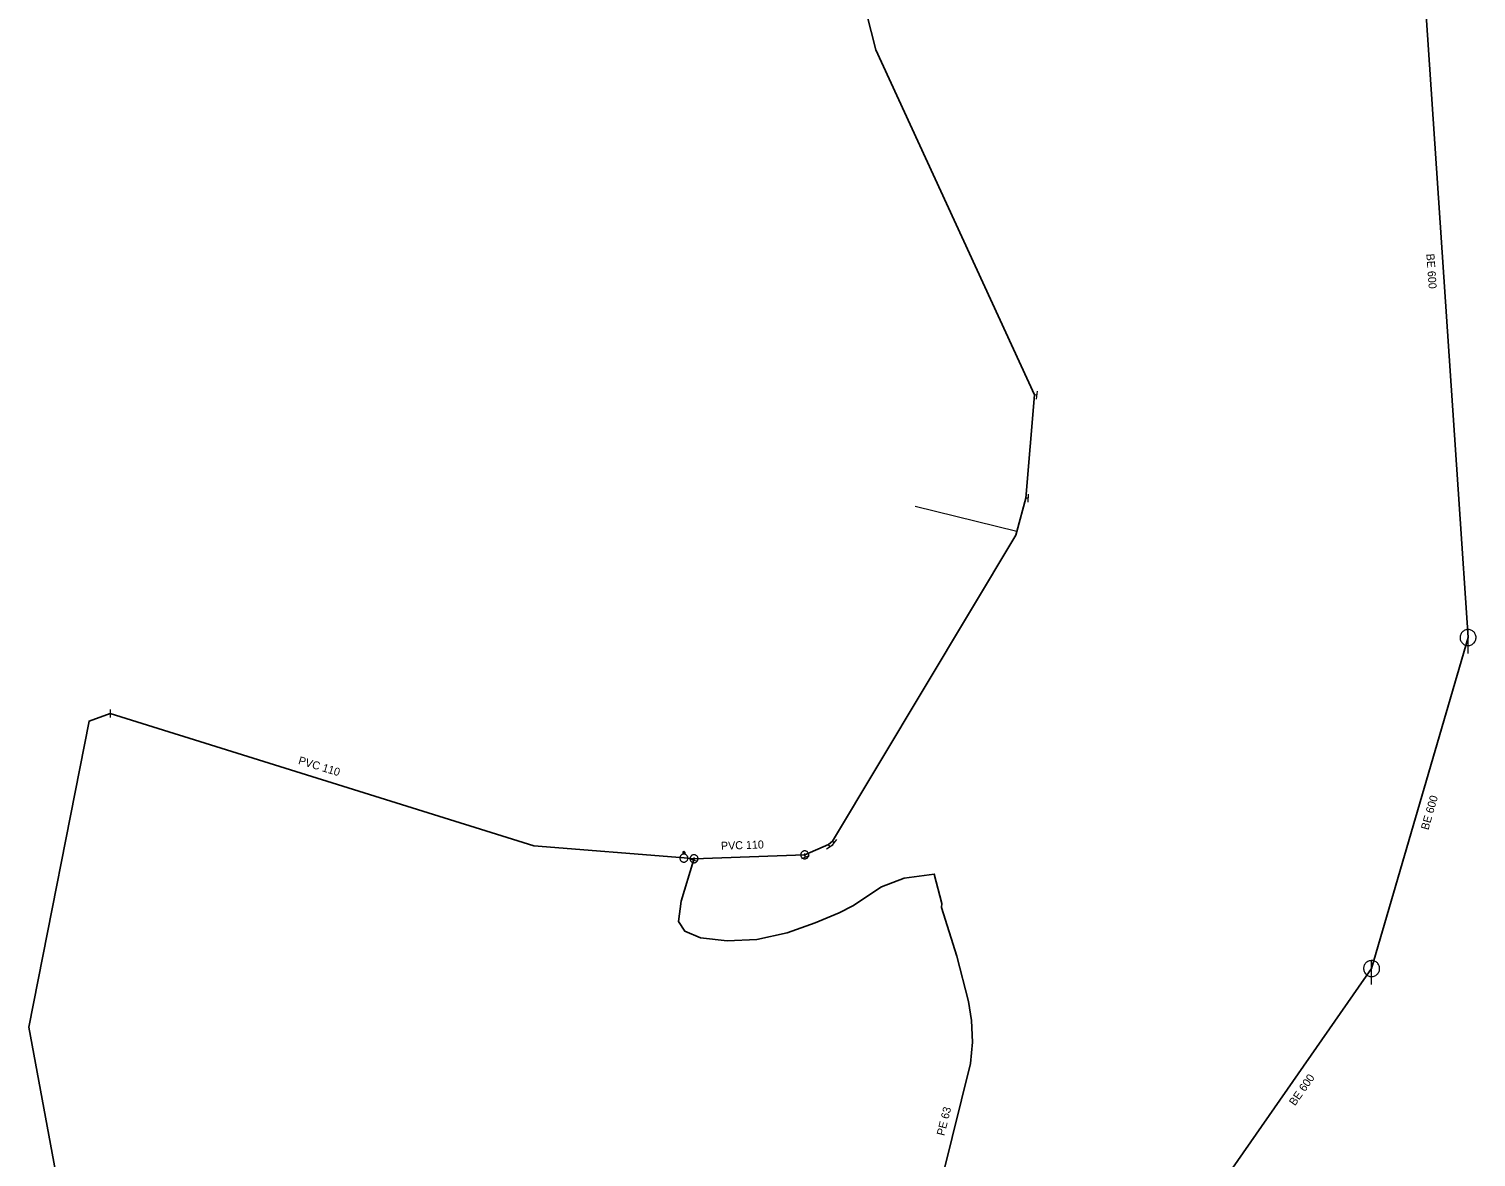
# Model space of a CAD drawing. Extents: x -659250 to -657316, y -997555 to -993684.
# Drawn here: x -658712.7 to -658531.9, y -994490.8 to -994349.9 of the extents above; entities that cross this region are included whole.
import ezdxf

# ---------------------------------------------------------------- set-up
doc = ezdxf.new("R2010")
doc.units = 0
doc.header["$LTSCALE"] = 0.4
doc.layers.add('1', color=7, linetype='Continuous')
for name, color, linetype, lineweight in [('13', 7, 'Continuous', 13), ('14', 7, 'Continuous', 25), ('17', 7, 'Continuous', 25), ('22', 7, 'Continuous', 13), ('23', 7, 'Continuous', 13), ('34', 7, 'Continuous', 13), ('47', 7, 'Continuous', 13)]:
    doc.layers.add(name, color=color, linetype=linetype, lineweight=lineweight)

msp = doc.modelspace()

# ---------------------------------------------------------------- linework, layer by layer
at = {"layer": '13'}
msp.add_line((-658589.278, -994412.67), (-658602.002, -994409.563), dxfattribs=at)
at = {"layer": '14', "lineweight": 13}
for p, q in [((-658586.789, -994395.629), (-658587.086, -994395.585)), ((-658587.859, -994408.51), (-658588.159, -994408.494)), ((-658612.66, -994452.039), (-658612.825, -994451.789)), ((-658612.1, -994451.55), (-658612.337, -994451.366)), ((-658629.622, -994453.55), (-658629.689, -994453.769)), ((-658615.69, -994453.34), (-658615.8, -994453.061))]:
    msp.add_line(p, q, dxfattribs=at)
at = {"layer": '14'}
msp.add_lwpolyline([(-658665.989, -994692.25), (-658669.32, -994646.26), (-658665.8, -994630.84), (-658645.039, -994594.649), (-658628.309, -994572.48), (-658618.039, -994539.21), (-658605.98, -994522.41), (-658563.96, -994494.52), (-658544.98, -994467.27), (-658532.93, -994425.92), (-658538.989, -994335.809)], dxfattribs=at)
at = {"layer": '17'}
for p, q in [((-658629.622, -994453.55), (-658630.87, -994453.45)), ((-658615.8, -994453.061), (-658629.622, -994453.55))]:
    msp.add_line(p, q, dxfattribs=at)
for points in [[(-658613.3, -994213.989), (-658613.524, -994214.403), (-658623.307, -994229.89), (-658624.14, -994257.537), (-658615.692, -994317.956), (-658606.899, -994352.517), (-658587.086, -994395.585), (-658588.159, -994408.494), (-658589.278, -994412.67), (-658589.404, -994413.139), (-658612.337, -994451.366), (-658612.825, -994451.789), (-658615.8, -994453.061)], [(-658702.57, -994435.41), (-658705.199, -994436.353), (-658712.71, -994474.592), (-658701.204, -994536.879), (-658692.771, -994555.022), (-658691.405, -994641.16), (-658677.627, -994701.215), (-658678.449, -994734.261), (-658664.614, -994780.175), (-658662.973, -994794.498), (-658662.386, -994819.574), (-658666.489, -994850.982), (-658664.028, -994890.978), (-658664.848, -994896.368), (-658669.708, -994912.272), (-658675.921, -994922.23), (-658689.166, -994922.67)], [(-658630.87, -994453.45), (-658649.618, -994451.947), (-658702.57, -994435.41)], [(-658629.689, -994453.769), (-658631.25, -994458.87), (-658631.57, -994461.379), (-658630.77, -994462.61), (-658628.829, -994463.44), (-658625.494, -994463.806), (-658621.773, -994463.622), (-658617.987, -994462.818), (-658614.486, -994461.561), (-658611.497, -994460.305), (-658609.78, -994459.44), (-658606.21, -994457.059), (-658603.359, -994455.96), (-658599.62, -994455.469), (-658598.66, -994459.129), (-658598.69, -994459.649), (-658596.8, -994465.719), (-658595.32, -994471.379), (-658594.949, -994473.75), (-658594.84, -994476.46), (-658595.09, -994479.149), (-658598.52, -994492.92)]]:
    msp.add_lwpolyline(points, dxfattribs=at)
at = {"layer": '22'}
for p, q in [((-658532.93, -994427.92), (-658532.929, -994424.92)), ((-658544.98, -994469.27), (-658544.979, -994466.27))]:
    msp.add_line(p, q, dxfattribs=at)
for points in [[(-658531.93, -994425.92), (-658531.935, -994425.811), (-658531.953, -994425.703), (-658531.983, -994425.597), (-658532.023, -994425.496), (-658532.075, -994425.399), (-658532.137, -994425.309), (-658532.209, -994425.226), (-658532.289, -994425.152), (-658532.377, -994425.086), (-658532.471, -994425.031), (-658532.571, -994424.986), (-658532.676, -994424.953), (-658532.783, -994424.931), (-658532.892, -994424.921), (-658533.002, -994424.923), (-658533.11, -994424.937), (-658533.217, -994424.962), (-658533.32, -994424.999), (-658533.418, -994425.048), (-658533.51, -994425.106), (-658533.596, -994425.175), (-658533.673, -994425.252), (-658533.742, -994425.338), (-658533.801, -994425.43), (-658533.849, -994425.528), (-658533.886, -994425.631), (-658533.912, -994425.738), (-658533.926, -994425.846), (-658533.929, -994425.956), (-658533.919, -994426.065), (-658533.898, -994426.172), (-658533.864, -994426.276), (-658533.82, -994426.376), (-658533.765, -994426.471), (-658533.699, -994426.559), (-658533.625, -994426.639), (-658533.542, -994426.711), (-658533.452, -994426.773), (-658533.356, -994426.825), (-658533.254, -994426.866), (-658533.149, -994426.896), (-658533.041, -994426.914), (-658532.931, -994426.92), (-658532.822, -994426.914), (-658532.714, -994426.896), (-658532.609, -994426.867), (-658532.507, -994426.826), (-658532.41, -994426.774), (-658532.32, -994426.712), (-658532.237, -994426.641), (-658532.162, -994426.561), (-658532.097, -994426.473), (-658532.041, -994426.379), (-658531.997, -994426.279), (-658531.963, -994426.175), (-658531.941, -994426.067), (-658531.931, -994425.958)], [(-658543.98, -994467.27), (-658543.985, -994467.161), (-658544.003, -994467.053), (-658544.033, -994466.947), (-658544.073, -994466.846), (-658544.125, -994466.749), (-658544.187, -994466.659), (-658544.259, -994466.576), (-658544.339, -994466.502), (-658544.427, -994466.436), (-658544.521, -994466.381), (-658544.621, -994466.336), (-658544.726, -994466.303), (-658544.833, -994466.281), (-658544.942, -994466.271), (-658545.052, -994466.273), (-658545.16, -994466.287), (-658545.267, -994466.312), (-658545.37, -994466.349), (-658545.468, -994466.398), (-658545.56, -994466.456), (-658545.646, -994466.525), (-658545.723, -994466.602), (-658545.792, -994466.688), (-658545.851, -994466.78), (-658545.899, -994466.878), (-658545.936, -994466.981), (-658545.962, -994467.088), (-658545.976, -994467.196), (-658545.979, -994467.306), (-658545.969, -994467.415), (-658545.948, -994467.522), (-658545.914, -994467.626), (-658545.87, -994467.726), (-658545.815, -994467.821), (-658545.749, -994467.909), (-658545.675, -994467.989), (-658545.592, -994468.061), (-658545.502, -994468.123), (-658545.406, -994468.175), (-658545.304, -994468.216), (-658545.199, -994468.246), (-658545.091, -994468.264), (-658544.981, -994468.27), (-658544.872, -994468.264), (-658544.764, -994468.246), (-658544.659, -994468.217), (-658544.557, -994468.176), (-658544.46, -994468.124), (-658544.37, -994468.062), (-658544.287, -994467.991), (-658544.212, -994467.911), (-658544.147, -994467.823), (-658544.091, -994467.729), (-658544.047, -994467.629), (-658544.013, -994467.525), (-658543.991, -994467.417), (-658543.981, -994467.308)]]:
    msp.add_lwpolyline(points, close=True, dxfattribs=at)
at = {"layer": '23'}
msp.add_line((-658630.783, -994452.802), (-658630.979, -994452.802), dxfattribs=at)
for points in [[(-658630.979, -994452.899), (-658630.979, -994452.75), (-658630.88, -994452.599), (-658630.783, -994452.75), (-658630.783, -994452.899)], [(-658630.393, -994453.467), (-658630.395, -994453.414), (-658630.404, -994453.362), (-658630.419, -994453.313), (-658630.438, -994453.264), (-658630.462, -994453.218), (-658630.492, -994453.174), (-658630.525, -994453.134), (-658630.562, -994453.098), (-658630.603, -994453.065), (-658630.647, -994453.037), (-658630.694, -994453.013), (-658630.744, -994452.995), (-658630.794, -994452.982), (-658630.845, -994452.975), (-658630.897, -994452.972), (-658630.951, -994452.976), (-658631.001, -994452.984), (-658631.053, -994452.999), (-658631.1, -994453.017), (-658631.147, -994453.041), (-658631.191, -994453.072), (-658631.231, -994453.105), (-658631.268, -994453.143), (-658631.301, -994453.183), (-658631.328, -994453.227), (-658631.351, -994453.275), (-658631.369, -994453.323), (-658631.382, -994453.374), (-658631.389, -994453.426), (-658631.393, -994453.478), (-658631.39, -994453.53), (-658631.381, -994453.582), (-658631.367, -994453.633), (-658631.348, -994453.681), (-658631.323, -994453.726), (-658631.294, -994453.77), (-658631.261, -994453.811), (-658631.223, -994453.848), (-658631.182, -994453.88)], [(-658631.053, -994452.999), (-658631.1, -994453.017), (-658631.147, -994453.041), (-658631.191, -994453.072), (-658631.231, -994453.105), (-658631.268, -994453.143), (-658631.301, -994453.183), (-658631.328, -994453.227), (-658631.351, -994453.275), (-658631.369, -994453.323), (-658631.382, -994453.374), (-658631.389, -994453.426), (-658631.393, -994453.478), (-658631.39, -994453.53), (-658631.381, -994453.582), (-658631.367, -994453.633), (-658631.348, -994453.681), (-658631.323, -994453.726), (-658631.294, -994453.77), (-658631.261, -994453.811), (-658631.223, -994453.848), (-658631.182, -994453.88), (-658631.139, -994453.908), (-658631.091, -994453.931), (-658631.043, -994453.95), (-658630.991, -994453.962), (-658630.94, -994453.969), (-658630.888, -994453.972), (-658630.836, -994453.968), (-658630.784, -994453.96), (-658630.733, -994453.946), (-658630.685, -994453.926), (-658630.638, -994453.902), (-658630.595, -994453.874), (-658630.555, -994453.839), (-658630.518, -994453.803), (-658630.486, -994453.762), (-658630.457, -994453.717), (-658630.434, -994453.67), (-658630.416, -994453.621)], [(-658631.182, -994453.88), (-658631.139, -994453.908), (-658631.091, -994453.931), (-658631.043, -994453.95), (-658630.991, -994453.962), (-658630.94, -994453.969), (-658630.888, -994453.972), (-658630.836, -994453.968), (-658630.784, -994453.96), (-658630.733, -994453.946), (-658630.685, -994453.926), (-658630.638, -994453.902), (-658630.595, -994453.874), (-658630.555, -994453.839), (-658630.518, -994453.803), (-658630.486, -994453.762), (-658630.457, -994453.717), (-658630.434, -994453.67), (-658630.416, -994453.621), (-658630.404, -994453.57), (-658630.396, -994453.519), (-658630.393, -994453.467), (-658630.395, -994453.414), (-658630.404, -994453.362), (-658630.419, -994453.313), (-658630.438, -994453.264), (-658630.462, -994453.218), (-658630.492, -994453.174), (-658630.525, -994453.134), (-658630.562, -994453.098), (-658630.603, -994453.065), (-658630.647, -994453.037), (-658630.694, -994453.013), (-658630.744, -994452.995), (-658630.794, -994452.982), (-658630.845, -994452.975), (-658630.897, -994452.972), (-658630.951, -994452.976), (-658631.001, -994452.984), (-658631.053, -994452.999)], [(-658630.416, -994453.621), (-658630.404, -994453.57), (-658630.396, -994453.519), (-658630.393, -994453.467)]]:
    msp.add_lwpolyline(points, dxfattribs=at)
at = {"layer": '34'}
for p, q in [((-658586.862, -994396.123), (-658586.714, -994395.134)), ((-658587.883, -994409.009), (-658587.833, -994408.01)), ((-658702.57, -994434.91), (-658702.57, -994435.91)), ((-658613.077, -994452.314), (-658612.242, -994451.764)), ((-658612.405, -994451.945), (-658611.793, -994451.154)), ((-658629.21, -994453.914), (-658630.166, -994453.622)), ((-658616.158, -994453.513), (-658615.22, -994453.167))]:
    msp.add_line(p, q, dxfattribs=at)
at = {"layer": '47'}
for points in [[(-658615.3, -994453.061), (-658615.303, -994453.009), (-658615.311, -994452.956), (-658615.325, -994452.907), (-658615.343, -994452.858), (-658615.367, -994452.811), (-658615.396, -994452.767), (-658615.429, -994452.727), (-658615.466, -994452.69), (-658615.506, -994452.657), (-658615.55, -994452.628), (-658615.597, -994452.603), (-658615.646, -994452.586), (-658615.696, -994452.572), (-658615.748, -994452.564), (-658615.8, -994452.561), (-658615.852, -994452.564), (-658615.904, -994452.572), (-658615.955, -994452.586), (-658616.003, -994452.603), (-658616.05, -994452.628), (-658616.094, -994452.657), (-658616.135, -994452.69), (-658616.172, -994452.727), (-658616.205, -994452.767), (-658616.233, -994452.811), (-658616.257, -994452.858), (-658616.276, -994452.907), (-658616.289, -994452.956), (-658616.297, -994453.009), (-658616.3, -994453.061), (-658616.297, -994453.113), (-658616.289, -994453.165), (-658616.276, -994453.216), (-658616.257, -994453.264), (-658616.233, -994453.311), (-658616.205, -994453.355), (-658616.172, -994453.396), (-658616.135, -994453.433), (-658616.094, -994453.466), (-658616.05, -994453.494), (-658616.003, -994453.518), (-658615.955, -994453.537), (-658615.904, -994453.549), (-658615.852, -994453.558), (-658615.8, -994453.561), (-658615.748, -994453.558), (-658615.696, -994453.549), (-658615.646, -994453.537), (-658615.597, -994453.518), (-658615.55, -994453.494), (-658615.506, -994453.466), (-658615.466, -994453.433), (-658615.429, -994453.396), (-658615.396, -994453.355), (-658615.367, -994453.311), (-658615.343, -994453.264), (-658615.325, -994453.216), (-658615.311, -994453.165), (-658615.303, -994453.113)], [(-658630.12, -994453.51), (-658630.121, -994453.562), (-658630.117, -994453.614), (-658630.107, -994453.665), (-658630.093, -994453.715), (-658630.073, -994453.764), (-658630.048, -994453.81), (-658630.018, -994453.853), (-658629.984, -994453.893), (-658629.947, -994453.929), (-658629.905, -994453.961), (-658629.86, -994453.989), (-658629.813, -994454.011), (-658629.764, -994454.029), (-658629.713, -994454.041), (-658629.661, -994454.048), (-658629.609, -994454.049), (-658629.557, -994454.045), (-658629.505, -994454.035), (-658629.456, -994454.021), (-658629.407, -994454.001), (-658629.361, -994453.976), (-658629.317, -994453.946), (-658629.277, -994453.912), (-658629.241, -994453.875), (-658629.21, -994453.833), (-658629.182, -994453.788), (-658629.159, -994453.741), (-658629.142, -994453.692), (-658629.13, -994453.641), (-658629.123, -994453.589), (-658629.122, -994453.537), (-658629.126, -994453.485), (-658629.135, -994453.433), (-658629.15, -994453.384), (-658629.17, -994453.335), (-658629.194, -994453.289), (-658629.224, -994453.245), (-658629.258, -994453.205), (-658629.296, -994453.169), (-658629.338, -994453.138), (-658629.383, -994453.11), (-658629.429, -994453.087), (-658629.479, -994453.07), (-658629.53, -994453.058), (-658629.582, -994453.051), (-658629.634, -994453.05), (-658629.686, -994453.054), (-658629.737, -994453.063), (-658629.787, -994453.078), (-658629.836, -994453.098), (-658629.882, -994453.122), (-658629.925, -994453.152), (-658629.965, -994453.186), (-658630.001, -994453.224), (-658630.033, -994453.266), (-658630.061, -994453.311), (-658630.083, -994453.357), (-658630.101, -994453.407), (-658630.113, -994453.458)], [(-658629.703, -994453.543), (-658629.704, -994453.552), (-658629.703, -994453.56), (-658629.701, -994453.568), (-658629.699, -994453.576), (-658629.696, -994453.585), (-658629.691, -994453.592), (-658629.687, -994453.599), (-658629.681, -994453.606), (-658629.675, -994453.611), (-658629.668, -994453.617), (-658629.66, -994453.622), (-658629.653, -994453.625), (-658629.645, -994453.628), (-658629.637, -994453.631), (-658629.628, -994453.631), (-658629.619, -994453.632), (-658629.611, -994453.631), (-658629.603, -994453.629), (-658629.595, -994453.627), (-658629.586, -994453.624), (-658629.579, -994453.619), (-658629.572, -994453.615), (-658629.565, -994453.609), (-658629.559, -994453.603), (-658629.554, -994453.596), (-658629.549, -994453.588), (-658629.546, -994453.581), (-658629.543, -994453.573), (-658629.54, -994453.565), (-658629.54, -994453.556), (-658629.539, -994453.547), (-658629.54, -994453.539), (-658629.542, -994453.531), (-658629.544, -994453.523), (-658629.547, -994453.514), (-658629.551, -994453.507), (-658629.556, -994453.5), (-658629.562, -994453.493), (-658629.568, -994453.487), (-658629.575, -994453.482), (-658629.583, -994453.477), (-658629.59, -994453.474), (-658629.598, -994453.471), (-658629.606, -994453.468), (-658629.615, -994453.468), (-658629.624, -994453.467), (-658629.632, -994453.468), (-658629.64, -994453.47), (-658629.648, -994453.472), (-658629.657, -994453.475), (-658629.664, -994453.479), (-658629.671, -994453.484), (-658629.678, -994453.49), (-658629.683, -994453.496), (-658629.689, -994453.503), (-658629.694, -994453.511), (-658629.697, -994453.518), (-658629.7, -994453.526), (-658629.703, -994453.534)], [(-658615.718, -994453.061), (-658615.718, -994453.052), (-658615.72, -994453.044), (-658615.722, -994453.036), (-658615.725, -994453.027), (-658615.729, -994453.02), (-658615.734, -994453.013), (-658615.739, -994453.005), (-658615.745, -994453), (-658615.752, -994452.995), (-658615.759, -994452.99), (-658615.767, -994452.986), (-658615.775, -994452.983), (-658615.783, -994452.981), (-658615.791, -994452.978), (-658615.8, -994452.978), (-658615.809, -994452.978), (-658615.817, -994452.981), (-658615.825, -994452.983), (-658615.833, -994452.986), (-658615.841, -994452.99), (-658615.848, -994452.995), (-658615.855, -994453), (-658615.861, -994453.005), (-658615.867, -994453.013), (-658615.871, -994453.02), (-658615.875, -994453.027), (-658615.878, -994453.036), (-658615.88, -994453.044), (-658615.882, -994453.052), (-658615.882, -994453.061), (-658615.882, -994453.07), (-658615.88, -994453.078), (-658615.878, -994453.086), (-658615.875, -994453.094), (-658615.871, -994453.102), (-658615.867, -994453.108), (-658615.861, -994453.116), (-658615.855, -994453.122), (-658615.848, -994453.128), (-658615.841, -994453.132), (-658615.833, -994453.136), (-658615.825, -994453.139), (-658615.817, -994453.141), (-658615.809, -994453.143), (-658615.8, -994453.143), (-658615.791, -994453.143), (-658615.783, -994453.141), (-658615.775, -994453.139), (-658615.767, -994453.136), (-658615.759, -994453.132), (-658615.752, -994453.128), (-658615.745, -994453.122), (-658615.739, -994453.116), (-658615.734, -994453.108), (-658615.729, -994453.102), (-658615.725, -994453.094), (-658615.722, -994453.086), (-658615.72, -994453.078), (-658615.718, -994453.07)]]:
    msp.add_lwpolyline(points, close=True, dxfattribs=at)

# ---------------------------------------------------------------- texts
at = {"layer": '1'}
for s, rotation, p in [('BE 600', 274, (-658538.141, -994378.004)), ('PVC 110 ', 343, (-658679.14, -994441.693)), ('BE 600', 74, (-658537.888, -994450.03)), ('PVC 110 ', 2, (-658626.243, -994452.444)), ('BE 600', 55, (-658554.555, -994484.49)), ('PE 63 ', 76, (-658598.365, -994488.221))]:
    msp.add_text(s, height=1, rotation=rotation, dxfattribs=at).set_placement(p)

doc.saveas('drawing.dxf')
